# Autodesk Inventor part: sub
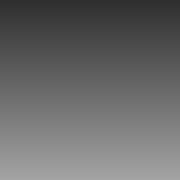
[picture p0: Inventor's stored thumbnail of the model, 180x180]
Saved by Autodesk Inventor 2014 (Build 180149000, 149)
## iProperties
Created: 2009-11
Part Number: sub
Document SubType Name: Modeling
Designer: pokornp
Density: 1 g/cm^3
Material: Generic
Appearance: Default
Author: pokornp
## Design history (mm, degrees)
sketch "Sketch1"
  geometry: L1 (0, 0)-(10000, 0); L2 (0, -1940)-(10000, -1940)
  constraints: 4 end point, 2 vertical alignment, 1 horizontal, 1 parallel
  dimensions: "d0" = 10000 dimension on L1.start L1.end L1 L2.start L2.end L2; "d0" = 10000 distance of L2.start L2.end; "d1" = 1940 distance between parallel lines of L2 L1
